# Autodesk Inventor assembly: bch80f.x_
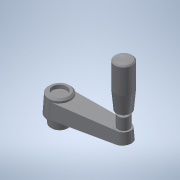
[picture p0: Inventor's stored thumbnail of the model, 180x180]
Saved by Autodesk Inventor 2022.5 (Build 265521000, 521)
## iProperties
Part Number: bch80f.x_
Material: 一般
Document SubType Name: Assembly
Designer: ImaoCorp
Sending System: SOLIDWORKS 2017-2017317
MC: AMD64
MC_MODEL: Intel64 Family 6 Model 60 Stepping 3, GenuineIntel
OS: Windows_NT
FRU: Parasolid Version 29.0, build 201,  4-17-2017
FORMAT: text
GUISE: transmit
KEY: bch80f
FILE: bch80f.x_t
DATE: Fri Mar 15 10:33:51 2019
Author: ImaoCorp
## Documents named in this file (3)
- X:\14_SW2022-Inv2022\00_全2023-1023新製品(TCC)まで\b\bch80f\BCH80F.iam
- X:\14_SW2022-Inv2022\00_全2023-1023新製品(TCC)まで\b\bch80f\bch80f_01.ipt
- X:\14_SW2022-Inv2022\00_全2023-1023新製品(TCC)まで\b\bch80f\bch80f_02.ipt
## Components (2 placed, 2 different names)
1. bch80f_01
2. bch80f_02
